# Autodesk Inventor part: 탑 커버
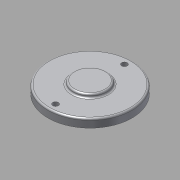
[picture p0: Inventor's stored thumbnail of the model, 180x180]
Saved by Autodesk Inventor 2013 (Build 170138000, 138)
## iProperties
Created: 2017-05
Part Number: 탑 커버
Material: 알루미늄 6061
Document SubType Name: Modeling
Designer: mduedu
Density: 1 g/cm^3
Author: mduedu
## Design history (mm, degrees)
sketch "스케치1"
  geometry: C1 r 25 at (0, 0); 1 further point
  constraints: 1 centre point, 1 coincident
  dimensions: "d31" = 50 diameter of C1
extrude "돌출1" new body sketch "스케치1" distance "d2" = 5; taper "d3" = 0 deg
sketch "스케치2"
  geometry: C1 r 10 at (0, 0); 1 further point
  constraints: 1 centre point, 1 coincident
  dimensions: "d5" = 20 diameter of C1
extrude "돌출2" join sketch "스케치2" distance "d6" = 2; taper "d7" = 0 deg
sketch "스케치3"
  geometry: C1 r 16 at (0, 0); 1 further point
  constraints: 1 centre point, 1 coincident
  dimensions: "d32" = 32 diameter of C1
extrude "돌출3" join sketch "스케치3" distance "d10" = 3; taper "d11" = 0 deg
sketch "스케치4"
  geometry: C1 r 16 at (0, 0) reference; C2 r 14 at (0, 0); 1 further point
  constraints: 1 centre point
  dimensions: "d33" = 2 radial gap between concentric circles of C2 C1
extrude "돌출4" cut sketch "스케치4" stored distance "d14" = 2; taper "d15" = 0 deg
chamfer "모따기1" distance "d16" = 1; stored, may be unused: second distance "d17" = 2, angle "d18" = 45 deg
fillet "모깎기3" dims "d19" = 1
fillet "모깎기4" dims "d20" = 1
fillet "모깎기5" dims "d21" = 1
sketch "스케치5" dims "d34" = 41
  geometry: C1 r 25 at (0, 0) reference; 2 further points
  constraints: 2 vertical alignment, 1 coincident, 2 other
hole "구멍2" sketch "스케치5" at (0, 20.5) diameter "d35" = 3.4; stored, may be unused: countersink angle "d39" = 90 deg, drill point angle "d41" = 118 deg; dims "d36" = 6, "d37" = 4, "d38" = 2, "d40" = 8
node "솔리드1"
pattern_circular "원형 패턴1" dims angle "d43" = 360 deg
node "투영된 루프2"
